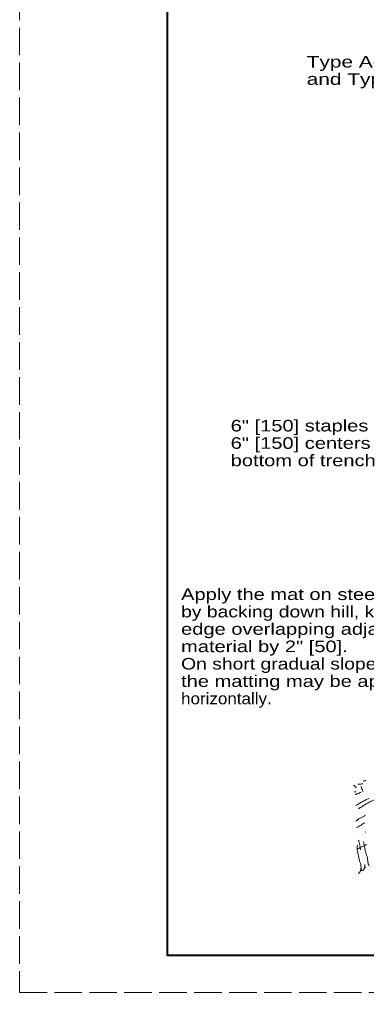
# Model space of a CAD drawing. Extents: x 1083.1 to 1117.1, y 719.4 to 741.4.
# Drawn here: x 1083.13 to 1087.81, y 719.35 to 732.5 of the extents above; entities that cross this region are included whole.
import ezdxf

# ---------------------------------------------------------------- set-up
doc = ezdxf.new("R2010")
doc.units = 0
doc.header["$LTSCALE"] = 0.062
doc.linetypes.add('LONG_DASHED', pattern=[7.5, 6, -1.5])
doc.layers.add('1', color=7, linetype='Continuous', lineweight=13)

msp = doc.modelspace()

# ---------------------------------------------------------------- linework, layer by layer
at = {"layer": '1', "linetype": 'LONG_DASHED'}
msp.add_lwpolyline([(1083.12642, 719.35408), (1117.12642, 719.35408), (1117.12642, 741.35408), (1083.12642, 741.35408)], close=True, dxfattribs=at)
at = {"layer": '1', "lineweight": 25}
msp.add_lwpolyline([(1116.62642, 719.85408), (1085.12642, 719.85408), (1085.12642, 740.85408)], dxfattribs=at)
at = {"layer": '1', "lineweight": 40}
msp.add_lwpolyline([(1085.12642, 740.85408), (1116.62642, 740.85408), (1116.62642, 719.85408), (1085.12642, 719.85408)], close=True, dxfattribs=at)
msp.add_lwpolyline([(1085.12642, 740.85408), (1116.62642, 740.85408), (1116.62642, 719.85408), (1085.12642, 719.85408)], close=True, dxfattribs=at)
at = {"layer": '1'}
for points in [[(1087.67867, 722.13133), (1087.66875, 722.12833), (1087.66075, 722.13033), (1087.65267, 722.14625), (1087.64667, 722.14925), (1087.63967, 722.14625)], [(1087.76233, 722.17425), (1087.75533, 722.17325), (1087.73833, 722.17025), (1087.72533, 722.16925), (1087.70842, 722.16825), (1087.7025, 722.16625)], [(1087.73858, 722.13633), (1087.74167, 722.12833), (1087.74767, 722.11142), (1087.75883, 722.0935), (1087.76183, 722.0815), (1087.767, 722.0635)], [(1087.80283, 722.21908), (1087.79492, 722.21508), (1087.774, 722.20908), (1087.77008, 722.20708)], [(1087.65117, 722.0605), (1087.65117, 722.0625), (1087.65317, 722.0655), (1087.65817, 722.0655), (1087.66417, 722.0645), (1087.66917, 722.0685)], [(1087.737, 722.0605), (1087.72808, 722.0555), (1087.70817, 722.04458), (1087.69025, 722.03967), (1087.67133, 722.03067), (1087.66342, 722.02467)], [(1087.84733, 721.97292), (1087.80158, 721.95492), (1087.75283, 721.927), (1087.724, 721.912), (1087.68425, 721.88817), (1087.66833, 721.87817)], [(1087.9835, 721.99475), (1087.96008, 721.97592), (1087.93125, 721.96292), (1087.90142, 721.95), (1087.8765, 721.938), (1087.85058, 721.92508), (1087.82375, 721.91008), (1087.79792, 721.89517), (1087.77317, 721.88017), (1087.75525, 721.86817), (1087.72742, 721.85125), (1087.7075, 721.83733)], [(1087.67367, 721.66975), (1087.68258, 721.67875), (1087.71733, 721.70375), (1087.73525, 721.71375), (1087.75417, 721.72475), (1087.77408, 721.73367), (1087.78992, 721.74267), (1087.79592, 721.74767)], [(1087.67817, 721.58117), (1087.70408, 721.59417), (1087.73983, 721.616), (1087.76575, 721.63092), (1087.7945, 721.64692), (1087.7975, 721.64792)], [(1087.79925, 721.52633), (1087.79925, 721.52533), (1087.79725, 721.52033)], [(1087.69167, 721.34483), (1087.688, 721.301), (1087.69317, 721.26417), (1087.69842, 721.23125), (1087.70567, 721.19433), (1087.71183, 721.1675), (1087.72508, 721.11858), (1087.73533, 721.08175), (1087.7385, 721.05183), (1087.74158, 721.034), (1087.74367, 721.019), (1087.74475, 721.008)], [(1087.698, 721.29508), (1087.70992, 721.30108), (1087.72883, 721.312), (1087.74575, 721.32), (1087.76267, 721.32692), (1087.78058, 721.33492), (1087.79642, 721.34392), (1087.80742, 721.35092), (1087.81233, 721.35392)], [(1087.70725, 721.41067), (1087.70933, 721.40075), (1087.71542, 721.38275), (1087.7195, 721.36483), (1087.72367, 721.33892), (1087.72683, 721.32), (1087.73092, 721.30008), (1087.734, 721.28217)], [(1087.77425, 721.39175), (1087.7815, 721.34292), (1087.79175, 721.29717), (1087.79792, 721.26817), (1087.80917, 721.22833), (1087.82142, 721.18942), (1087.82858, 721.15258), (1087.83175, 721.12567), (1087.83492, 721.10275), (1087.84408, 721.07775), (1087.85208, 721.06483)], [(1087.71958, 720.97717), (1087.73283, 721.003), (1087.73958, 721.032), (1087.74067, 721.017), (1087.74783, 721.002), (1087.76275, 721.004), (1087.7885, 721.03992), (1087.79217, 721.07575), (1087.79008, 721.08575)], [(1087.79225, 721.05883), (1087.79425, 721.05192), (1087.80333, 721.04392)], [(1087.69917, 720.96317), (1087.718, 720.97417), (1087.71958, 720.97717)]]:
    msp.add_spline(points, degree=3, dxfattribs=at)

# ---------------------------------------------------------------- texts
for s, width, p in [('Type A-F', 1.35, (1087.00608, 731.8485)), ('and Type H-I', 1.35, (1087.00608, 731.6145)), ('6" [150] staples on', 1.3, (1085.97925, 726.93275)), ('6" [150] centers across', 1.3, (1085.97925, 726.69808)), ('bottom of trench', 1.3, (1085.97925, 726.46342)), ('Apply the mat on steep slopes', 1.3, (1085.30958, 724.65575)), ('by backing down hill, keep the', 1.25, (1085.30958, 724.42108)), ('edge overlapping adjacent', 1.3, (1085.30958, 724.18642)), ('material by 2" [50].', 1.3, (1085.30958, 723.95175)), ('On short gradual slopes,', 1.25, (1085.30958, 723.71708)), ('the matting may be applied', 1.3, (1085.30958, 723.48242)), ('horizontally.', 1.1, (1085.30958, 723.24775))]:
    msp.add_text(s, height=0.156, dxfattribs=dict(at, width=width)).set_placement(p)

doc.saveas('drawing.dxf')
